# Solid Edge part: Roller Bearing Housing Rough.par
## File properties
Title: Roller Bearing Housing
Author: Dan
Template: Roller Bearing Housing.par
Last saved by: Dan
Revision: 17
Application: Solid Edge
Density: 7.85 kg/dm^3
Accuracy: 0.99
Document Number: P52-004-1
Project Name: Piston Pump P52
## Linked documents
Roller Bearing Housing.par
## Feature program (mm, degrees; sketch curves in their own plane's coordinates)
part copy "CopiedPart_1"
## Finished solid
Body 1: solid body, 17 faces, 17 edges, 0 vertices.
  Faces by surface: torus 6, cylinder 4, plane 4, cone 3
  Edges by curve: circle 17
Bounding box of the edges (mm; curved faces can reach further): 92.600 x 92.600 x 15.000, from (-46.3, -46.3, 0) to (46.3, 46.3, 15).
Cylindrical faces by radius (mm): R22 x2, R26.4 x1, R46.3 x1
Conical faces (half-angle, radius in mm at the cone's reference point): 27 deg R46.3 x1, 45 deg R22 x1, 45 deg R22.5 x1
Toroidal faces (ring radius, tube radius in mm): R23 r1 x2, R26.2 r0.6 x2, R39.7258 r1 x1, R45.3 r1 x1
Planar faces by outward normal: +z 2, -z 2
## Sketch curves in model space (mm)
line (0, -45.3, 0) -> (0, -23, 0)
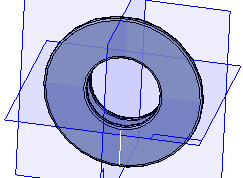
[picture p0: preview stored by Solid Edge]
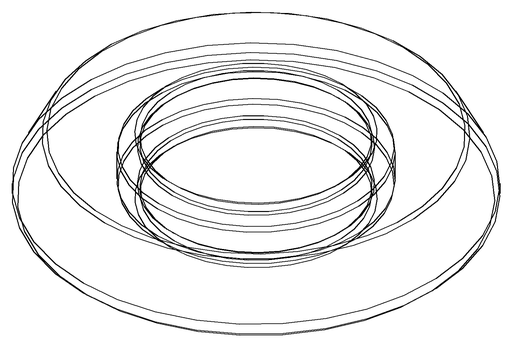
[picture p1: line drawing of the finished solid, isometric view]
